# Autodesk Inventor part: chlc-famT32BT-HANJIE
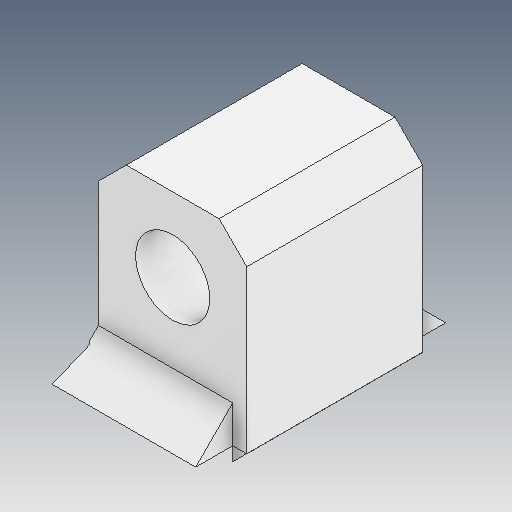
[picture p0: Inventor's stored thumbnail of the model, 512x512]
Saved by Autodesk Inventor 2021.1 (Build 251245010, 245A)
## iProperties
Created: 2021-05
Part Number: chlc-famT32BT-HANJIE
Material: Ogólny
Document SubType Name: Modeling
Designer: user
Density: 1 g/cm^3
Appearance: Domyślna
Author: user
Revision Number: ÈÎºÎ
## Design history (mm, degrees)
feature "ÊäÈë1"
feature "ÊäÈë2"
feature "ÊäÈë3"
node "Bryła1"
node "Bryła2"
node "Bryła3"
